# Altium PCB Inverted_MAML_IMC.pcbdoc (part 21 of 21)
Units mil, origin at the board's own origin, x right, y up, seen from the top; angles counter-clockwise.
Board outline 7677.1 x 6771.6 mil, 6 copper layers (Top Layer, Inner1, Inner2, Inner3, Inner4, Bottom Layer), stack 60.7 mil thick; 2732 components, 1531 nets, 7765 pads, 3705 vias.
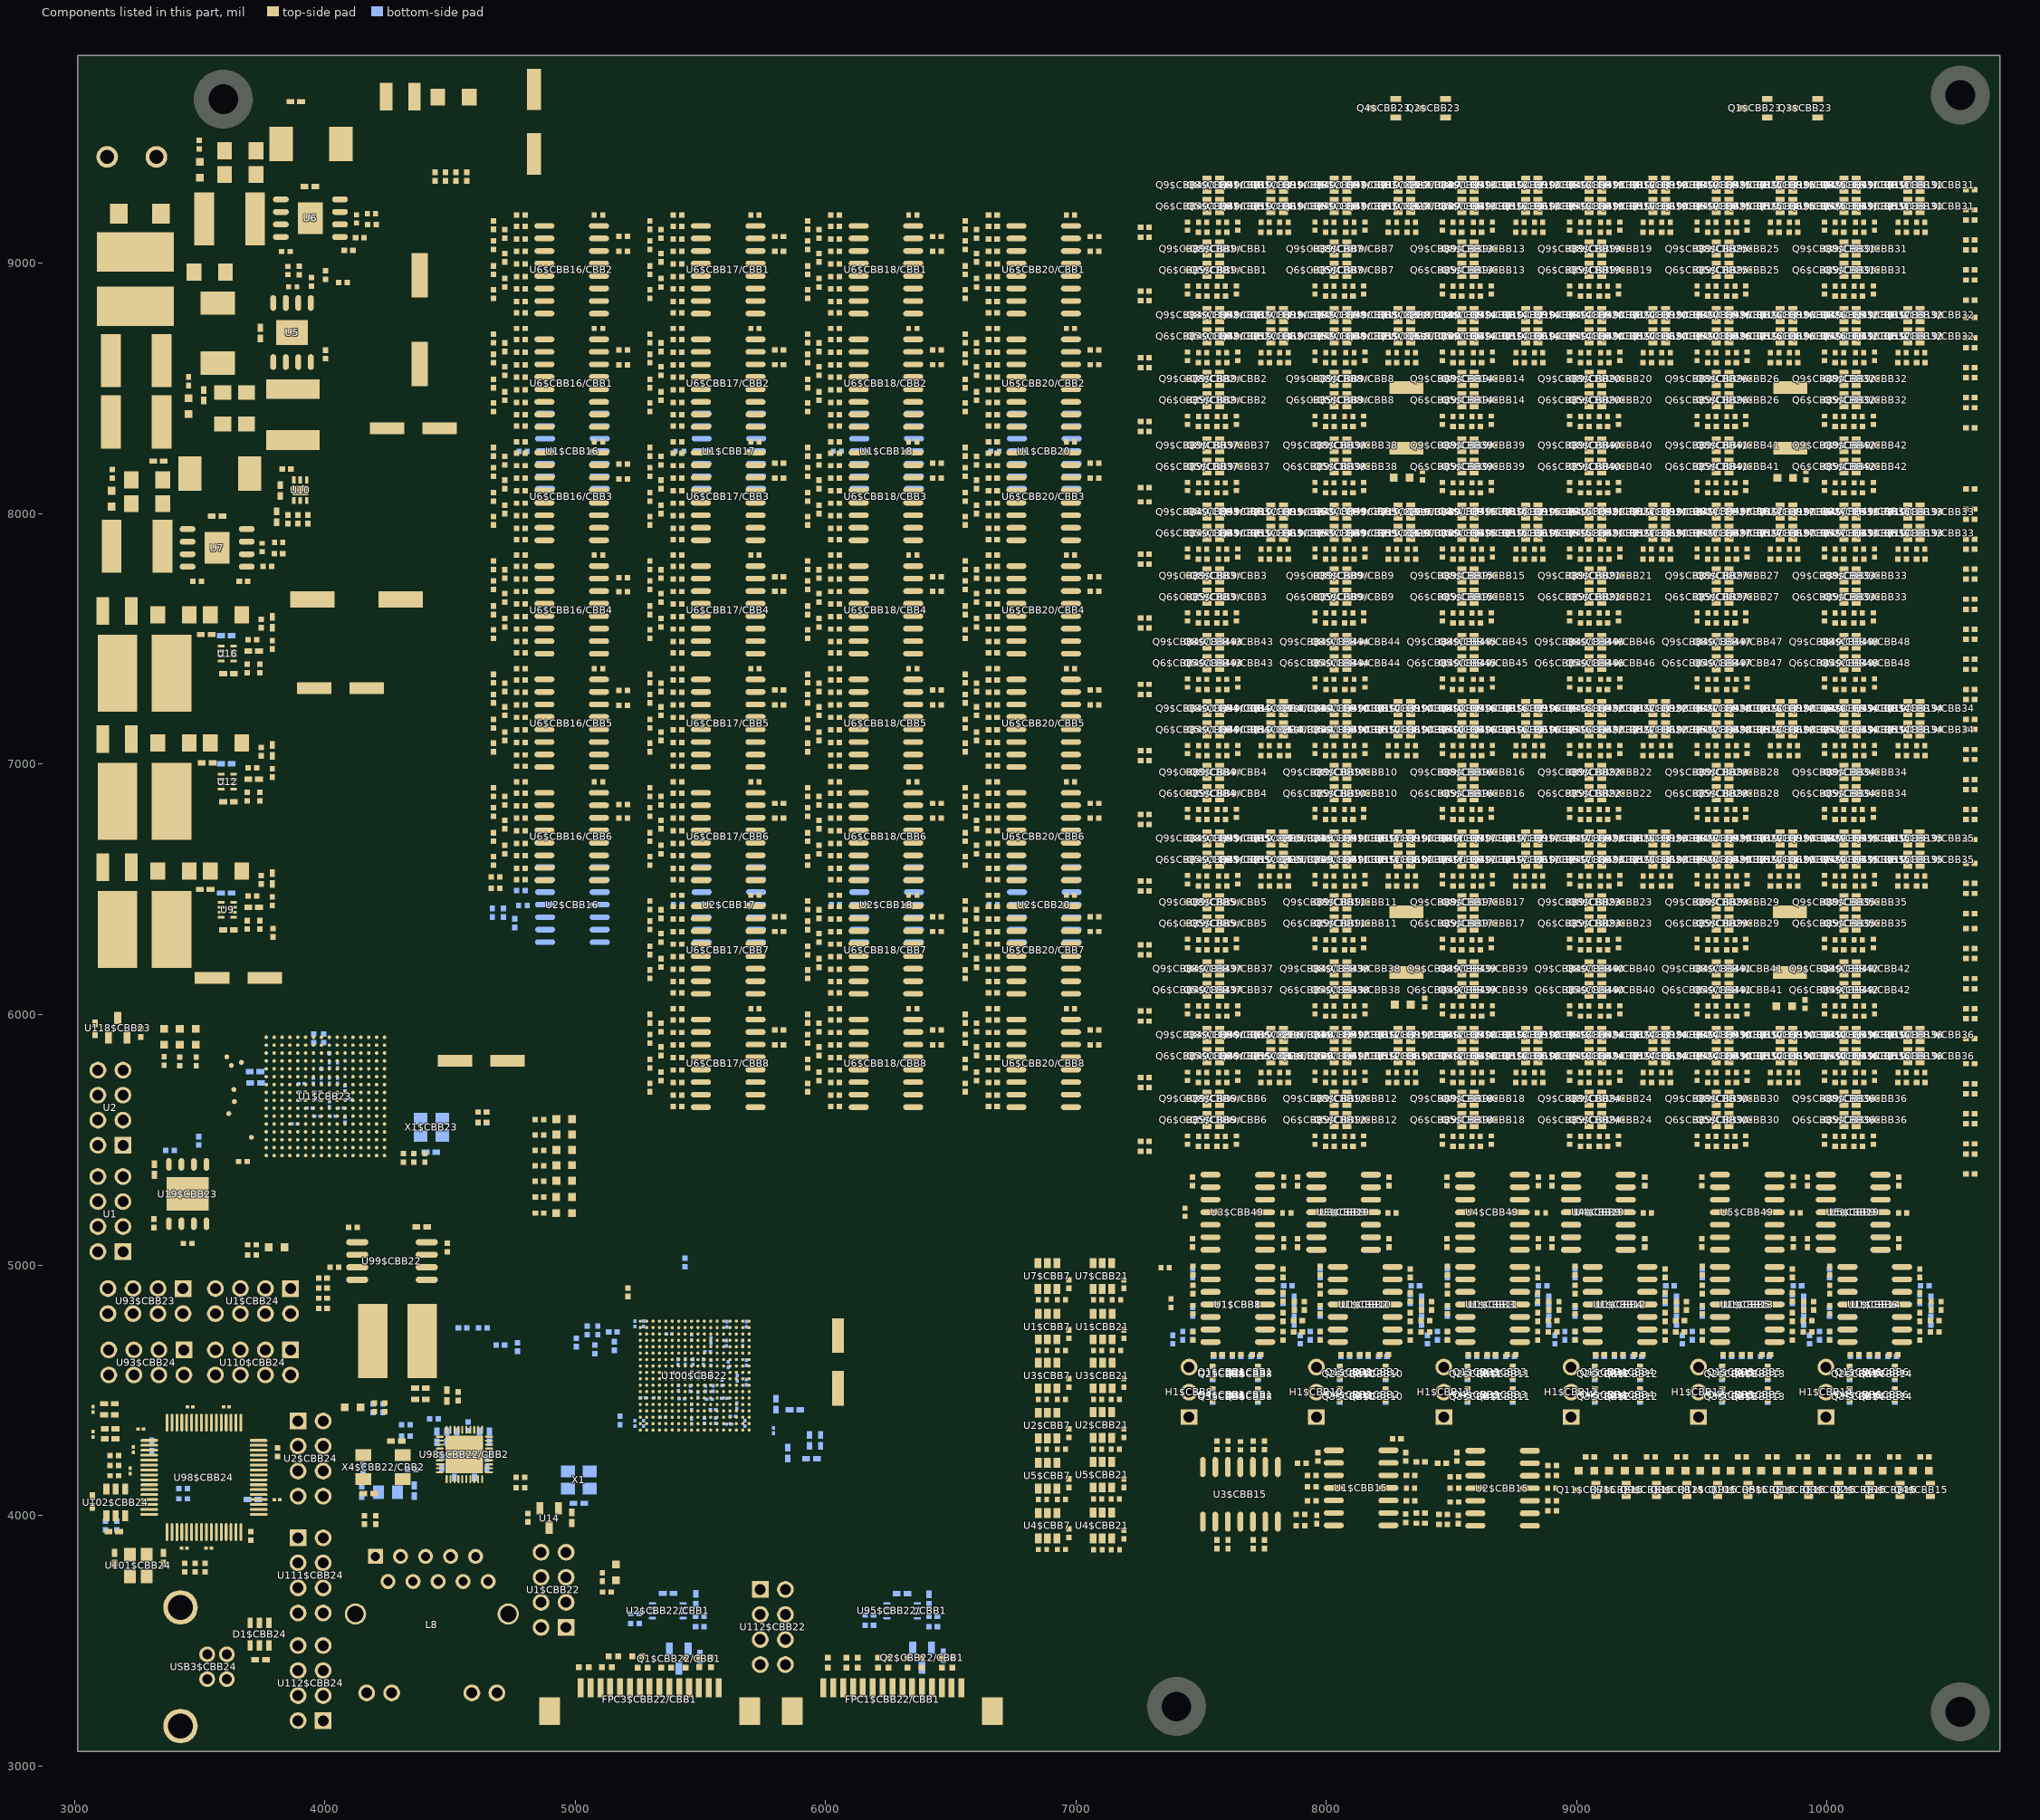
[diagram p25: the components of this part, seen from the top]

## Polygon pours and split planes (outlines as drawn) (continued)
1.8V on Inner2 (solid, remove dead copper): 5586.6,3664.6 5586.6,3670.2 5591,3674.6 5842,3674.6 5868.1,3700.7 5868.1,3702.3 5889.8,3724 5947.2,3724 5950.4,3720.8 5950.4,3670.6 5900.2,3620.4 5821.9,3620.4 5815.9,3626.4 5601,3626.4 5601,3650.1
3.3VD on Inner4 (solid, remove dead copper): 3970.9,5074.4 4021.9,5074.4 4055,5041.4 4055,4421.5 3956.6,4421.5 3950.6,4427.6 3950.6,5054.1
3.3VD on Inner2 (solid, remove dead copper): 3976.7,4501.6 4029.1,4501.6 4051.6,4479.1 4051.6,4297.2 4041.5,4287 3862.2,4287 3844.1,4305.1 3665.7,4305.1 3665.7,4494.1 3969.1,4494.1
3.3VD on Inner2 (solid, remove dead copper): 4154.4,4333.7 5210.6,4333.7 5257.7,4286.6 5257.7,4187.4 5084.2,4013.9 3689.5,4013.9 3677.5,4026 3677.5,4387.4 3692.3,4402.2 4085.8,4402.2
3.3V on Inner4 (solid, remove dead copper): 6962.1,9173.6 7081.4,9173.6 7086.9,9168.1 7086.9,5186.5 7080.8,5180.5 6948.3,5180.5 6940.3,5188.5 6940.3,9151.8
3.3V on Inner4 (solid, remove dead copper): 6817.8,3799.8 6817.8,5132.3 6833.9,5148.4 6833.9,5172.5 6892.1,5230.7 7421.5,5230.7 7421.5,3799.8
3.3V on Inner2 (solid, remove dead copper): 7042.7,5351.2 10648.8,5351.2 10656.8,5343.1 10656.8,5120.3 10642.8,5106.2 7042.7,5106.2
3.3V on Inner2 (solid, remove dead copper): 7280.6,4921.6 10241.1,4921.6 10243.2,4919.5 10271.3,4919.5 10277.4,4913.5 10277.4,4801 10272.1,4795.7 7280.6,4795.7
3.3V on Inner2 (solid, remove dead copper): 8870.9,4134.7 8870.9,4086.8 8871.6,4086.2 7631,4086.2 7631,4222.8 8185.3,4222.8 8248.4,4159.7 8424.9,4159.7 8444.2,4140.4 8463.4,4140.4 8473,4130.8 8867.1,4130.8
3.3V on Inner2 (solid, remove dead copper): 7645.6,4087.6 7219,4087.6 7109.9,4196.7 7060.7,4196.7 7022.6,4234.8 7022.6,4281 7035.8,4294.2 7166,4294.2 7235.4,4224.8 7653.1,4224.8 7663.1,4214.7 7663.1,4105.1
3.3VD on Top Layer (solid, remove dead copper, pour order 58): 4687.4,5726.7 4685.4,5728.7 4685.4,5800.9 4687.4,5803 4763.7,5803 4765.7,5800.9 4765.7,5742.7 4749.7,5726.7
GND on Inner2 (solid, remove dead copper): 3012.9,9829.8 3012.9,3058.2 10690,3058.2 10690,9829.8
GND on Inner4 (solid, remove dead copper): 3012.9,9829.8 3012.9,3058.2 10690,3058.2 10690,9829.8

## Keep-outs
Top Layer:
  region: 9897.9,3321.2 9897.9,3139.8 10278.4,3139.8 10278.4,3321.2
  region: 5038.8,3357.4 5052.9,3371.4 5052.9,3569.2 5362.6,3878.9 5362.6,3919.9 5399.9,3957.2 5435.7,3957.2 5506.3,4027.7 5506.3,4322 5672.5,4322 5677.3,4317.1 5677.3,3919.6 5343.5,3585.7 5343.5,3392.4 5344.4,3391.5 5344.4,3379.1 5360.1,3363.4 5360.1,3263 5354.1,3257 5273.7,3257 5269.6,3261.1 5269.6,3350.5 5287.8,3368.7 5287.8,3522 5283.8,3526 5227.6,3526 5227.6,3403.3 5224.8,3400.6 5224.8,3377.9 5244.9,3357.8 5244.9,3265 5234.9,3255 5167.3,3255 5161.3,3261 5161.3,3349.3 5175.4,3363.4 5175.4,3377.4 5173.3,3379.4 5173.3,3526 5109.1,3526 5107.1,3524 5107.1,3373.4 5109.1,3373.4 5126.8,3355.7 5126.8,3265 5116.8,3255 5046.9,3255 5038.8,3263
  region: 4205.6,3682.4 4205.6,3932.9 4409.6,4136.9 4660.9,4136.9 4693.5,4104.3 4693.5,3847.3 4603.1,3756.9 4603.1,3678.6 4209.3,3678.6
Inner1:
  region: 9897.1,3321.2 9897.1,3138.7 10278.3,3138.7 10278.3,3321.2
Inner2:
  region: 9897.2,3321.2 9897.2,3139.7 10278.3,3139.7 10278.3,3321.2
Inner3:
  region: 9897.7,3321.2 9897.7,3139.7 10279.3,3139.7 10279.3,3321.2
Inner4:
  region: 9897.7,3321.2 9897.7,3138.7 10278.3,3138.7 10278.3,3321.2
Bottom Layer:
  region: 9897.9,3321.2 9897.9,3139.8 10278.4,3139.8 10278.4,3321.2
Board Outline Layer:
  the board outline again, w10

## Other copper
Top Layer:
  pour cut-out: 5242,4796.2 5242,4322.1 5716,4322.1 5716,4796.2
  pour cut-out: 3748.3,5928.7 3748.3,5418.4 4258.5,5418.4 4258.5,5928.7
  region net GND: 9954.3,3235.7 9889.9,3235.7 9889.9,3134.8 9954.3,3134.8
  text "1" at 9920.3,3243.7 h59.1
Inner1:
  pour cut-out: 5242,4796.2 5242,4322.1 5716,4322.1 5716,4796.2
  pour cut-out: 3748.3,5928.7 3748.3,5418.4 4258.5,5418.4 4258.5,5928.7
  region net GND: 10014.3,3215.7 9890.3,3215.7 9890.3,3127.7 10014.3,3127.7
  text "2" at 9976.3,3243.7 h59.1
Inner2:
  pour cut-out: 5242,4796.2 5242,4322.1 5716,4322.1 5716,4796.2
  pour cut-out: 3748.3,5928.7 3748.3,5418.4 4258.5,5418.4 4258.5,5928.7
  region net GND: 10075.3,3197.7 9890.3,3197.7 9890.3,3133.1 10075.3,3133.1
  text "3" at 10035.3,3242.7 h59.1
Inner3:
  pour cut-out: 5242,4796.2 5242,4322.1 5716,4322.1 5716,4796.2
  pour cut-out: 3748.3,5928.7 3748.3,5418.4 4258.5,5418.4 4258.5,5928.7
  region net GND: 10143.3,3178.7 9890.3,3178.7 9890.3,3133.6 10143.3,3133.6
  text "4" at 10096.3,3241.7 h59.1
Inner4:
  pour cut-out: 5242,4796.2 5242,4322.1 5716,4322.1 5716,4796.2
  pour cut-out: 3748.3,5928.7 3748.3,5418.4 4258.5,5418.4 4258.5,5928.7
  region net GND: 10209.3,3158.7 9890.3,3158.7 9890.3,3133.1 10209.3,3133.1
  text "5" at 10162.3,3241.7 h59.1
Bottom Layer:
  pour cut-out: 5242,4796.2 5242,4322.1 5716,4322.1 5716,4796.2
  pour cut-out: 3748.3,5928.7 3748.3,5418.4 4258.5,5418.4 4258.5,5928.7
  text "6" at 10229.3,3242.7 h59.1

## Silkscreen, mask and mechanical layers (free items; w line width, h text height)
Top Silkscreen Layer:
  lines w5.9: 3370.3,6110.2 3392.4,6110.2 3421.3,6081.3 3421.3,5987
  lines w11.8: 4057,4275 4101.1,4275 4109.2,4283
  text "GND" at 3059.1,9575.7 h59.1
  text "+12V" at 3267.9,9575.7 h59.1
  text "Inverted MAML Analog 2T1C Matrix (6x6) / Matrix Multiplication with Proprioception / Proof-of-Concept PCB for Future ASIC | Patent Pending: SE 2630397-4" at 5066.9,9190.2 h120
  text "DONE T20" at 3605.2,5108.2 h51.2
  text "T20 / JTAG" at 3994.7,4977.7 h51.2 r90
  text "T120 / JTAG" at 4030.9,4546 h51.2 r90
  text "JTAG PROG" at 3183.5,4451.7 h51.2
  text "T20 / RES" at 4085.1,4285 h51.2
  text "T120 / RES" at 3715.6,3756.9 h51.2
  text "Source code and documentation link: / https://github.com/ollewelin/analog_matrix_computation_Inverted_MAML_PAT_PEND_2630397-4" at 6855.9,3481.9 h78.7
  text "Layer Order" at 9909.3,3329.7 h59.1
  text "Inventor and designer : Olle Welin / Inverted_MAML_IMC version 1.1 / Date: 2026-09-04" at 7815.7,3084.3 h120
